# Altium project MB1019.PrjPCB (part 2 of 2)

## Sheet ST_LINK.SCHDOC
size A4; Revision: C.1
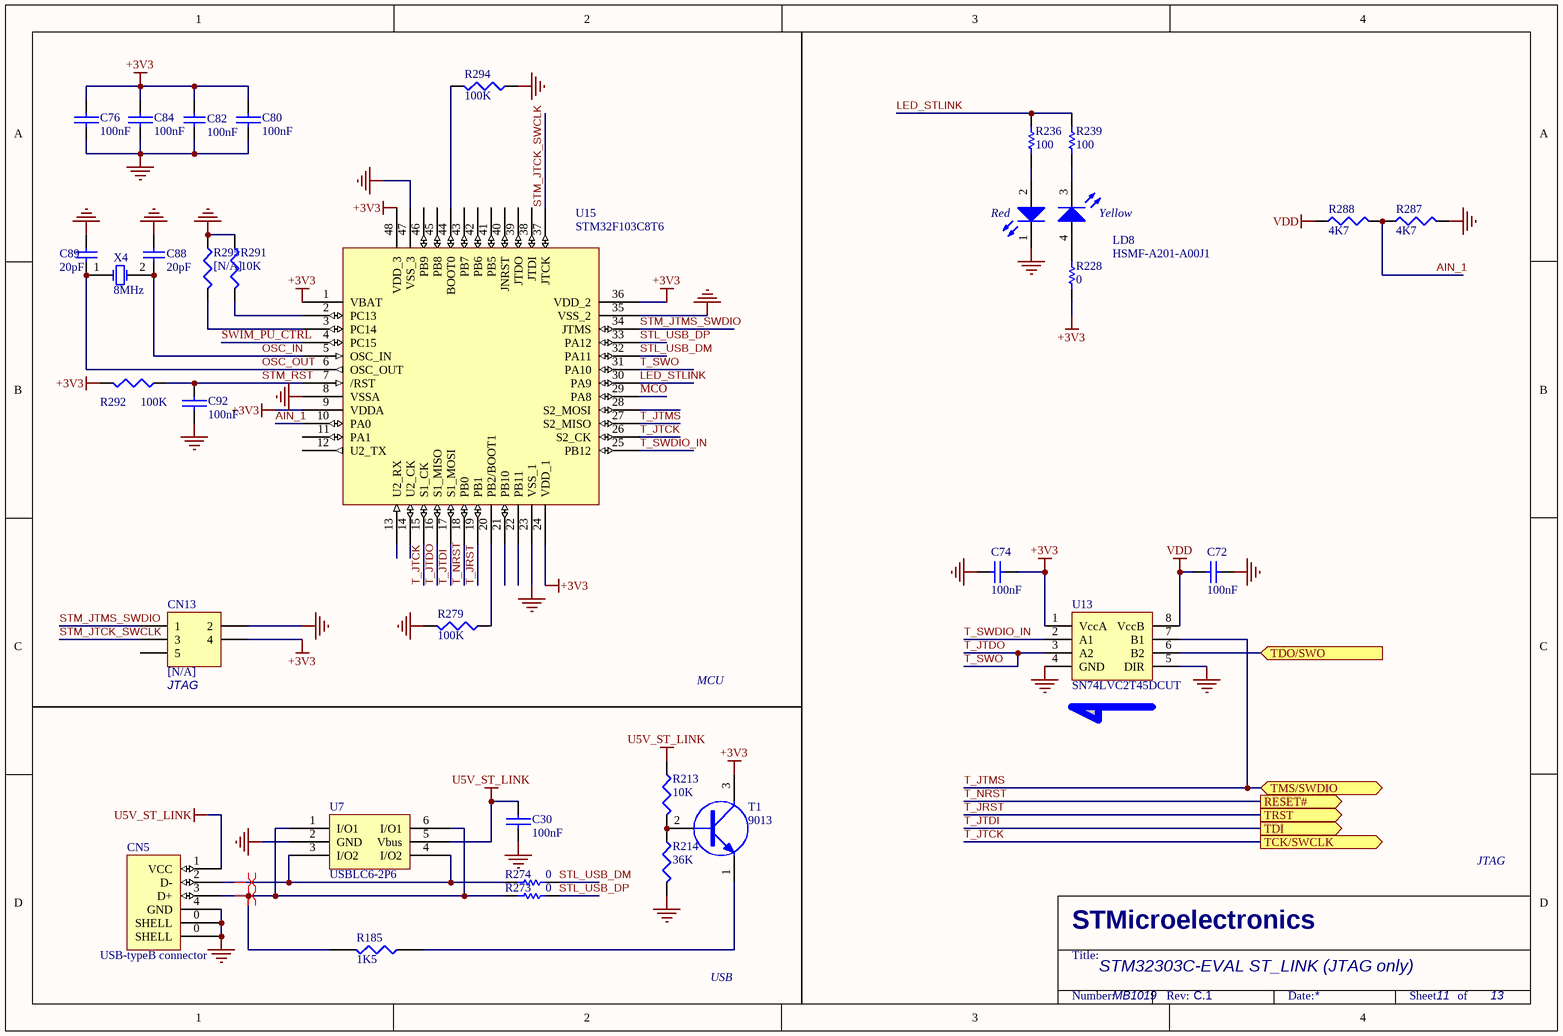
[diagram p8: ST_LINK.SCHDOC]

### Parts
C30  100nF  [0603C]
C72  100nF  [0603C]
C74  100nF  [0603C]
C76  100nF  [0603C]
C80  100nF  [0603C]
C82  100nF  [0603C]
C84  100nF  [0603C]
C88  20pF  [0603C]
C89  20pF  [0603C]
C92  100nF  [0603C]
CN5  USB-typeB connector  [USB-B]
CN13  [N/A]  [2*3P]
LD8  HSMF-A201-A00J1  [LED2-28*32]
R185  1K5  [0603R]
R213  10K  [0603R]
R214  36K  [0603R]
R228  0  [0603R]
R236  100  [0603R]
R239  100  [0603R]
R273  0  [0603R]
R274  0  [0603R]
R279  100K  [0603R]
R287  4K7  [0603R]
R288  4K7  [0603R]
R291  10K  [0603R]
R292  100K  [0603R]
R294  100K  [0603R]
R295  [N/A]  [0603R]
T1  9013  [SOT-23]
U7  USBLC6-2P6  [SOT-666]
U13  SN74LVC2T45DCUT  [VSSOP8]
U15  STM32F103C8T6  [LQFP48]
X4  8MHz  [SMT_XTAL]

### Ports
RESET# (out), TCK/SWCLK (out), TDI (out), TDO/SWO (in), TMS/SWDIO (bidir), TRST (out)

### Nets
+3V3: C74.2 C76.2 C80.2 C82.1 C84.2 CN13.4 R228.2 R292.2 T1.3(C) U13.1(VccA) U15.1(VBAT) U15.9(VDDA) U15.24(VDD_1) U15.36(VDD_2) U15.48(VDD_3)
GND: C30.2 C72.2 C74.1 C76.1 C80.1 C82.2 C84.1 C88.1 C89.1 C92.1 CN5.0(SHELL) CN5.4(GND) CN13.2 LD8.1(RED_cathode) R214.2 R279.2 R287.2 R291.1 R294.1 R295.1 U7.2(GND) U13.4(GND) U13.5(DIR) U15.8(VSSA) U15.23(VSS_1) U15.35(VSS_2) U15.47(VSS_3)
U5V_ST_LINK: C30.1 CN5.1(VCC) R213.1 U7.5(Vbus)
VDD: C72.1 R288.1 U13.8(VccB)
AIN_1: R287.1 R288.2 U15.10(PA0)
LED_STLINK: R236.1 R239.1 U15.30(PA9)
MCO: U15.29(PA8)
OSC_IN: C88.2 U15.5(OSC_IN) X4.2(OSC2)
OSC_OUT: C89.2 U15.6(OSC_OUT) X4.1(OSC1)
PB3: U13.6(B2) ; port TDO/SWO
STL_USB_DM: R274.1 U15.32(PA11)
STL_USB_DP: R273.1 U15.33(PA12)
STM_JTCK_SWCLK: CN13.3 U15.37(JTCK)
STM_JTMS_SWDIO: CN13.1 U15.34(JTMS)
STM_RST: C92.2 R292.1 U15.7(/RST)
SWIM_PU_CTRL: U15.4(PC15)
T_JRST: U15.19(PB1) ; port TRST  [project net PB4]
T_JTCK: U15.15(S1_CK) U15.26(S2_CK) ; port TCK/SWCLK  [project net PA14]
T_JTDI: U15.17(S1_MOSI) ; port TDI  [project net PA15]
T_JTDO: U13.3(A2) U15.16(S1_MISO) U15.31(PA10)  [also labelled T_SWO]
T_JTMS: U13.7(B1) U15.27(S2_MISO) ; port TMS/SWDIO  [project net PA13]
T_NRST: U15.18(PB0) ; port RESET#  [project net RESET#]
T_SWDIO_IN: U13.2(A1) U15.25(PB12)
NetCN5_2: CN5.2(D-) R274.2 U7.3(I/O2) U7.4(I/O2)
NetCN5_3: CN5.3(D+) R185.2 R273.2 U7.1(I/O1) U7.6(I/O1)
NetLD8_2: LD8.2(Red_anode) R236.2
NetLD8_3: LD8.3(YellowGreen_cathode) R239.2
NetLD8_4: LD8.4(YellowGreen_anode) R228.1
NetR185_1: R185.1 T1.1(E)
NetR213_2: R213.2 R214.1 T1.2(B)
NetR279_1: R279.1 U15.20(PB2/BOOT1)
NetR291_2: R291.2 U15.2(PC13)
NetR294_2: R294.2 U15.44(BOOT0)
NetR295_2: R295.2 U15.3(PC14)

Not connected (* = marked no-connect by the designer): CN13 5; U15 11(PA1) 12(U2_TX) 13(U2_RX) 14(U2_CK) 21(PB10) 22(PB11) 28(S2_MOSI) 38(JTDI) 39(JTDO) 40(JNRST) 41(PB5) 42(PB6) 43(PB7) 45(PB8) 46(PB9)

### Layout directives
differential pair: NetCN5_2, NetCN5_3

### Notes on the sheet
- (near CN13) JTAG
- MCU
- JTAG
- USB
- STM32303C-EVAL ST_LINK (JTAG only)
- MB1019
- 11
- 13

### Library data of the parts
C30 = CAP: Capacitor
C72 C74 = CAP: Capacitor; Value: 100pF
C76 C80 C84 C92 = CAP
C82 = Cap: Capacitor; Value: 10nF
C88 C89 = Cap: Capacitor
CN13 = Header 3X2: Header, 3-Pin, Dual row
R185 R279 R287 R288 R292 R294 = RES1
R213 R214 R291 R295 = R: Right: 20; Bottom: 30
R228 R236 R239 R273 R274 = Res1: Resistor; Value: 1K
T1 = NPN
U7 = USBLC6-2
U15 = STM32F10x(48pin)
X4 = XTAL: Crystal Oscillator

## Sheet Power.SchDoc
size A4; Revision: C.1
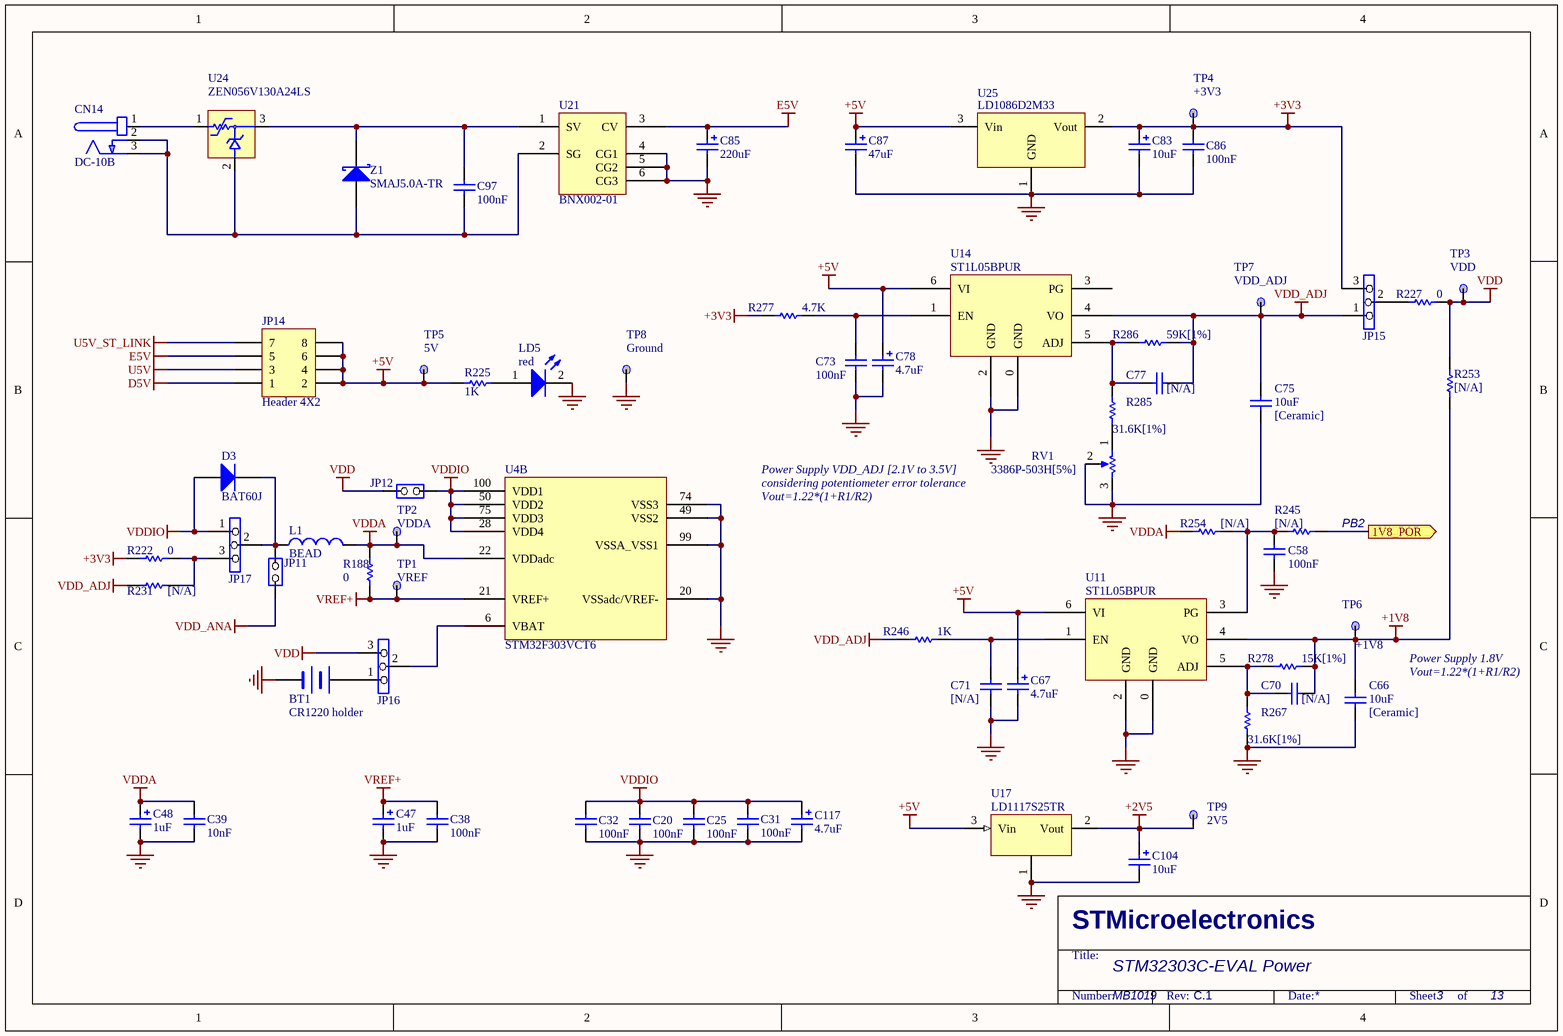
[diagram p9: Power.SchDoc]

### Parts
BT1  CR1220 holder  [LI1220_1]
C20  100nF  [0603C]
C25  100nF  [0603C]
C31  100nF  [0603C]
C32  100nF  [0603C]
C38  100nF  [0603C]
C39  10nF  [0603C]
C47  1uF  [TAN-A]
C48  1uF  [TAN-A]
C58  100nF  [0603C]
C66  10uF  [0805C]
C67  4.7uF  [TAN-A]
C70  [N/A]  [0603C]
C71  [N/A]  [0603C]
C73  100nF  [0603C]
C75  10uF  [0805C]
C77  [N/A]  [0603C]
C78  4.7uF  [TAN-A]
C83  10uF  [TAN-A]
C85  220uF  [C310M]
C86  100nF  [0603C]
C87  47uF  [C200M]
C97  100nF  [0603C]
C104  10uF  [TAN-A]
C117  4.7uF  [TAN-A]
CN14  DC-10B  [DC10B]
D3  BAT60J  [SOD-323]
JP11  (no value)  [SIP2]
JP12  (no value)  [SIP2]
JP14  Header 4X2  [2*4P]
JP15  (no value)  [SIP3]
JP16  (no value)  [SIP3]
JP17  (no value)  [SIP3]
L1  BEAD  [0603L]
LD5  red  [0603D]
R188  0  [0603R]
R222  0  [0603R]
R225  1K  [0603R]
R227  0  [0603R]
R231  [N/A]  [0603R]
R245  [N/A]  [0603R]
R246  1K  [0603R]
R253  [N/A]  [0603R]
R254  [N/A]  [0603R]
R267  31.6K[1%]  [0603R]
R277  4.7K  [0603R]
R278  15K[1%]  [0603R]
R285  31.6K[1%]  [0603R]
R286  59K[1%]  [0603R]
RV1  3386P-503H[5%]  [3296W]
TP1  VREF  [TP]
TP2  VDDA  [TP]
TP3  VDD  [TP]
TP4  +3V3  [TP]
TP5  5V  [TP]
TP6  +1V8  [TP]
TP7  VDD_ADJ  [TP]
TP8  Ground  [TP]
TP9  2V5  [TP]
U4  STM32F303VCT6  [IC149-100-025-B5]  (part B of 2)
U11  ST1L05BPUR  [DFN6(3X3)]
U14  ST1L05BPUR  [DFN6(3X3)]
U17  LD1117S25TR  [SOT-223]
U21  BNX002-01  [BNX001]
U24  ZEN056V130A24LS  [polyzen]
U25  LD1086D2M33  [D2PAK/A]
Z1  SMAJ5.0A-TR  [1R1C]

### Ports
1V8_POR (out)

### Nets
+1V8: C66.1 C70.2 R253.2 R278.1 TP6.1 U11.4(VO)
+2V5: C104.1 TP9.1 U17.2(Vout)
+3V3: C83.1 C86.1 JP15.3 R222.2 R277.2 TP4.1 U25.2(Vout)
+5V: C67.1 C78.1 C87.1 JP14.2 JP14.4 JP14.6 JP14.8 R225.2 TP5.1 U11.6(VI) U14.6(VI) U17.3(Vin) U25.3(Vin)
D5V: JP14.1
E5V: C85.1 JP14.5 U21.3(CV)
GND: BT1.2(-) C20.2 C25.2 C31.1 C32.2 C38.1 C39.1 C47.2 C48.2 C58.2 C66.2 C67.2 C71.2 C73.2 C75.2 C78.2 C83.2 C85.2 C86.2 C87.2 C104.2 C117.2 LD5.2(K) R267.2 RV1.2(TAP) RV1.3(TOP) TP8.1 U4.20(VSSadc/VREF-) U4.49(VSS2) U4.74(VSS3) U4.99(VSSA_VSS1) U11.0(GND) U11.2(GND) U14.0(GND) U14.2(GND) U17.1 U21.4(CG1) U21.5(CG2) U21.6(CG3) U25.1(GND)
U5V: JP14.3
U5V_ST_LINK: JP14.7
VDD: JP12.2(NO) JP16.3 R227.1 R253.1 TP3.1
VDD_ADJ: C75.1 C77.2 JP15.1 R231.2 R246.2 R286.1 TP7.1 U14.4(VO)
VDD_ANA: JP11.1(COMMON)
VDDA: C39.2 C48.1 L1.2 R188.1 R254.1 TP2.1 U4.22(VDDadc)
VDDIO: C20.1 C25.1 C31.2 C32.1 C117.1 D3.1(A) JP12.1(COMMON) JP17.1 U4.28(VDD4) U4.50(VDD2) U4.75(VDD3) U4.100(VDD1)
VREF+: C38.2 C47.1 R188.2 TP1.1 U4.21(VREF+)
PB2: R245.1 ; port 1V8_POR
NetBT1_1: BT1.1(+) JP16.1
NetC58_1: C58.1 R245.2 R254.2 U11.3(PG)
NetC70_1: C70.1 R267.1 R278.2 U11.5(ADJ)
NetC71_1: C71.1 R246.1 U11.1(EN)
NetC73_1: C73.1 R277.1 U14.1(EN)
NetC77_1: C77.1 R285.1 R286.2 U14.5(ADJ)
NetC97_1: C97.1 U21.1(SV) U24.3 Z1.2(K)
NetC97_2: C97.2 CN14.2(GND) CN14.3(GND) U21.2(SG) U24.2 Z1.1(A)
NetCN14_1: CN14.1(+) U24.1
NetD3_2: D3.2(K) JP11.2(NO) JP17.2 L1.1
NetJP15_2: JP15.2 R227.2
NetJP16_2: JP16.2 U4.6(VBAT)
NetJP17_3: JP17.3 R222.1 R231.1
NetLD5_1: LD5.1(A) R225.1
NetR285_2: R285.2 RV1.1(BOT)

Not connected (* = marked no-connect by the designer): U14 3(PG)

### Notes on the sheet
- (near C75) [Ceramic]
- Power Supply VDD_ADJ [2.1V to 3.5V]
- Vout=1.22*(1+R1/R2)
- considering potentiometer error tolerance
- (near R245) PB2
- (near C66) [Ceramic]
- Power Supply 1.8V
- STM32303C-EVAL Power
- MB1019
- 3
- 13

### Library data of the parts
BT1 = BATTERY
C20 C25 C32 = CAP: Capacitor
C31 C38 C58 C66 C70 C71 C73 C75 C77 C86 = Cap: Capacitor; Value: 10nF
C39 = Cap: Capacitor
C47 C48 C87 = Cap Pol1: Polarized Capacitor (Radial); Value: 10uF
C67 C78 C117 = Cap Pol1: Polarized Capacitor (Radial); Value: 100pF
C83 C104 = Cap Pol1: Polarized Capacitor (Radial)
C85 = Cap Pol1: Polarized Capacitor (Radial); Value: 47uF
C97 = CAP: Capacitor; Value: 100pF
CN14 = PJ202A
D3 = Diode: Default Diode; Code - JEDEC: DO-214-AB
JP11 JP12 = JP2
JP14 = Header 4X2: Header, 4-Pin, Dual row
JP15-JP17 = Jumper3
L1 = Inductor: Value: 100uH
LD5 = LED2: Typical RED, GREEN, YELLOW, AMBER GaAs LED
R188 R222 R227 R231 R245 R253 R267 R278 R285 R286 = Res1: Resistor; Value: 1K
R225 R246 = res1: Resistor
R254 R277 = res1: Resistor; Value: 1K
RV1 = RV
TP1-TP9 = TP
U11 U14 = ST1L05
U17 = LD1117
U21 = BNX002
U25 = VOLTREG1
Z1 = D Schottky: Schottky Diode; Code - JEDEC: DO-214-AA

## Sheet Audio.SchDoc
size A4; Revision: C.1
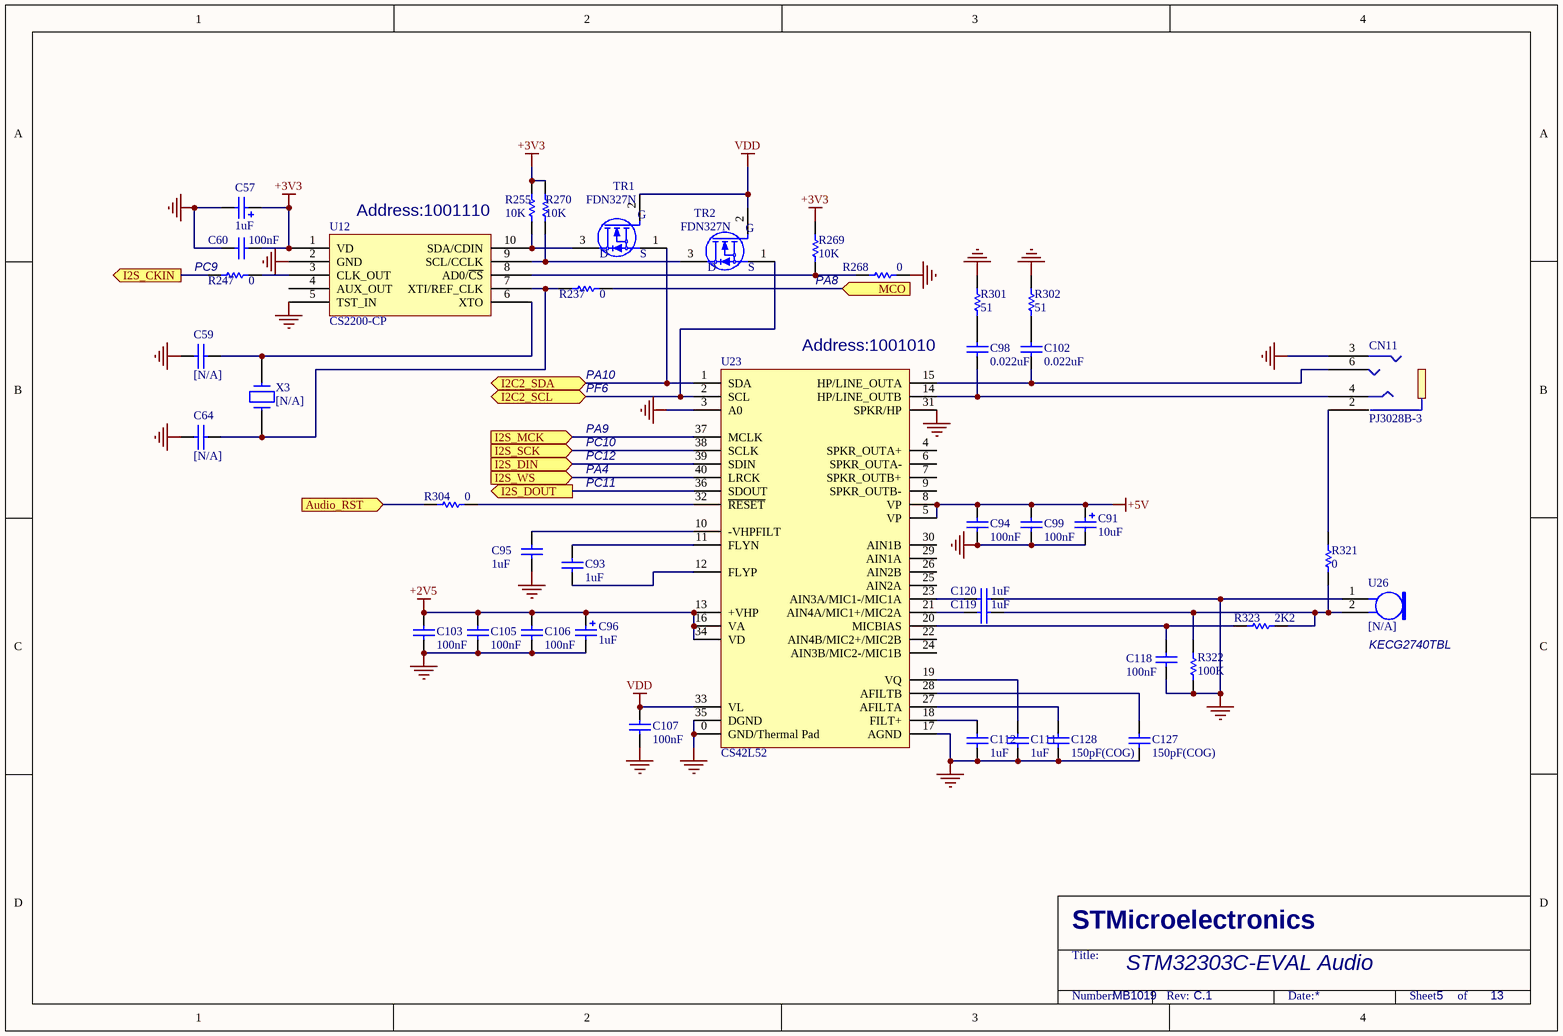
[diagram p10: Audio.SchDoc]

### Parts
C57  1uF  [TAN-A]
C59  [N/A]  [0603C]
C60  100nF  [0603C]
C64  [N/A]  [0603C]
C91  10uF  [TAN-A]
C93  1uF  [0603C]
C94  100nF  [0603C]
C95  1uF  [0603C]
C96  1uF  [TAN-A]
C98  0.022uF  [0603C]
C99  100nF  [0603C]
C102  0.022uF  [0603C]
C103  100nF  [0603C]
C105  100nF  [0603C]
C106  100nF  [0603C]
C107  100nF  [0603C]
C111  1uF  [0603C]
C112  1uF  [0603C]
C118  100nF  [0603C]
C119  1uF  [0603C]
C120  1uF  [0603C]
C127  150pF(COG)  [0603C]
C128  150pF(COG)  [0603C]
CN11  PJ3028B-3  [PJ3028B]
R237  0  [0603R]
R247  0  [0603R]
R255  10K  [0603R]
R268  0  [0603R]
R269  10K  [0603R]
R270  10K  [0603R]
R301  51  [0603R]
R302  51  [0603R]
R304  0  [0603R]
R321  0  [0603R]
R322  100K  [0603R]
R323  2K2  [0603R]
TR1  FDN327N  [SOT-23]
TR2  FDN327N  [SOT-23]
U12  CS2200-CP  [MSOP10(0.5)]
U23  CS42L52  [QFN40(6*6)]
U26  [N/A]  [KEC2740]
X3  [N/A]  [XTAL_socket]

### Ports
Audio_RST (in), I2C2_SCL (bidir), I2C2_SDA (bidir), I2S_CKIN (out), I2S_DIN (in), I2S_DOUT (out), I2S_MCK (in), I2S_SCK (in), I2S_WS (in), MCO (in)

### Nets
+2V5: C96.1 C103.1 C105.1 C106.1 U23.13(+VHP) U23.16(VA) U23.34(VD)
+3V3: C57.1 C60.1 R255.1 R269.1 R270.1 U12.1(VD)
+5V: C91.1 C94.1 C99.1 U23.5(VP) U23.8(VP)
GND: C57.2 C59.2 C60.2 C64.2 C91.2 C94.2 C95.2 C96.2 C99.2 C103.2 C105.2 C106.2 C107.2 C111.1 C112.1 C118.2 C120.2 C127.1 C128.1 CN11.3 R268.1 R301.1 R302.1 R322.2 U12.2(GND) U12.5(TST_IN) U23.0(GND/Thermal_Pad) U23.3(A0) U23.17(AGND) U23.31(SPKR/HP) U23.35(DGND) U26.1
VDD: C107.1 TR1.2(G) TR2.2(G) U23.33(VL)
PA8: R237.1 ; port MCO
PC9: R247.2 ; port I2S_CKIN
RESET#: R304.2 ; port Audio_RST
NetC59_1: C59.1 U12.6(XTO) X3.2
NetC64_1: C64.1 R237.2 U12.7(XTI/REF_CLK) X3.1
NetC93_1: C93.1 U23.12(FLYP)
NetC93_2: C93.2 U23.11(FLYN)
NetC95_1: C95.1 U23.10(-VHPFILT)
NetC98_1: C98.1 R301.2
NetC98_2: C98.2 CN11.4 U23.14(HP/LINE_OUTB)
NetC102_1: C102.1 R302.2
NetC102_2: C102.2 CN11.6 U23.15(HP/LINE_OUTA)
NetC111_2: C111.2 U23.19(VQ)
NetC112_2: C112.2 U23.18(FILT+)
NetC118_1: C118.1 R323.2 U23.20(MICBIAS)
NetC119_1: C119.1 U23.21(AIN4A/MIC1+/MIC2A)
NetC119_2: C119.2 R321.1 R322.1 R323.1 U26.2
NetC120_1: C120.1 U23.23(AIN3A/MIC1-/MIC1A)
NetC127_2: C127.2 U23.28(AFILTB)
NetC128_2: C128.2 U23.27(AFILTA)
NetCN11_2: CN11.2 R321.2
NetJP5_1: TR1.1(S) U23.1(SDA) ; port I2C2_SDA
NetJP6_1: TR2.1(S) U23.2(SCL) ; port I2C2_SCL
NetJP18_1: U23.37(MCLK) ; port I2S_MCK
NetR16_2: U23.40(LRCK) ; port I2S_WS
NetR52_1: U23.38(SCLK) ; port I2S_SCK
NetR54_1: U23.36(SDOUT) ; port I2S_DOUT
NetR56_1: U23.39(SDIN) ; port I2S_DIN
NetR247_1: R247.1 U12.3(CLK_OUT)
NetR255_2: R255.2 TR1.3(D) U12.10(SDA/CDIN)
NetR268_2: R268.2 R269.2 U12.8(AD0/~{CS})
NetR270_2: R270.2 TR2.3(D) U12.9(SCL/CCLK)
NetR304_1: R304.1 U23.32(~{RESET})

Not connected (* = marked no-connect by the designer): U12 4(AUX_OUT); U23 4(SPKR_OUTA+) 6(SPKR_OUTA-) 7(SPKR_OUTB+) 9(SPKR_OUTB-) 22(AIN4B/MIC2+/MIC2B) 24(AIN3B/MIC2-/MIC1B) 25(AIN2A) 26(AIN2B) 29(AIN1A) 30(AIN1B)

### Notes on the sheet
- (near U12) Address:1001110
- (near R247) PC9
- (near R269) PA8
- PA10
- (near U23) Address:1001010
- PA9
- PC10
- PF6
- PA4
- PC12
- PC11
- (near U26) KECG2740TBL
- STM32303C-EVAL Audio
- MB1019
- 5
- 13

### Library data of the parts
C57 C96 = Cap Pol1: as C85 on sheet Power
C59 C60 C64 = CAP: Capacitor
C91 = Cap Pol1: Polarized Capacitor (Radial)
C93 C95 C98 C102 C111 C112 C119 C120 C127 C128 = CAP: Capacitor; Value: 100nF
C94 C99 C103 C105-C107 C118 = Cap: Capacitor; Value: 10nF
R237 R268 R301 R302 R321 R322 = res1: Resistor; Value: 1K
R247 R255 R269 R270 R304 R323 = Res1: Resistor; Value: 1K
TR1 TR2 = 2N7000
U26 = Mic2: Microphone
X3 = CRYSTAL

## Sheet I2C Peripherals.SCHDOC
size A4; Revision: C.1
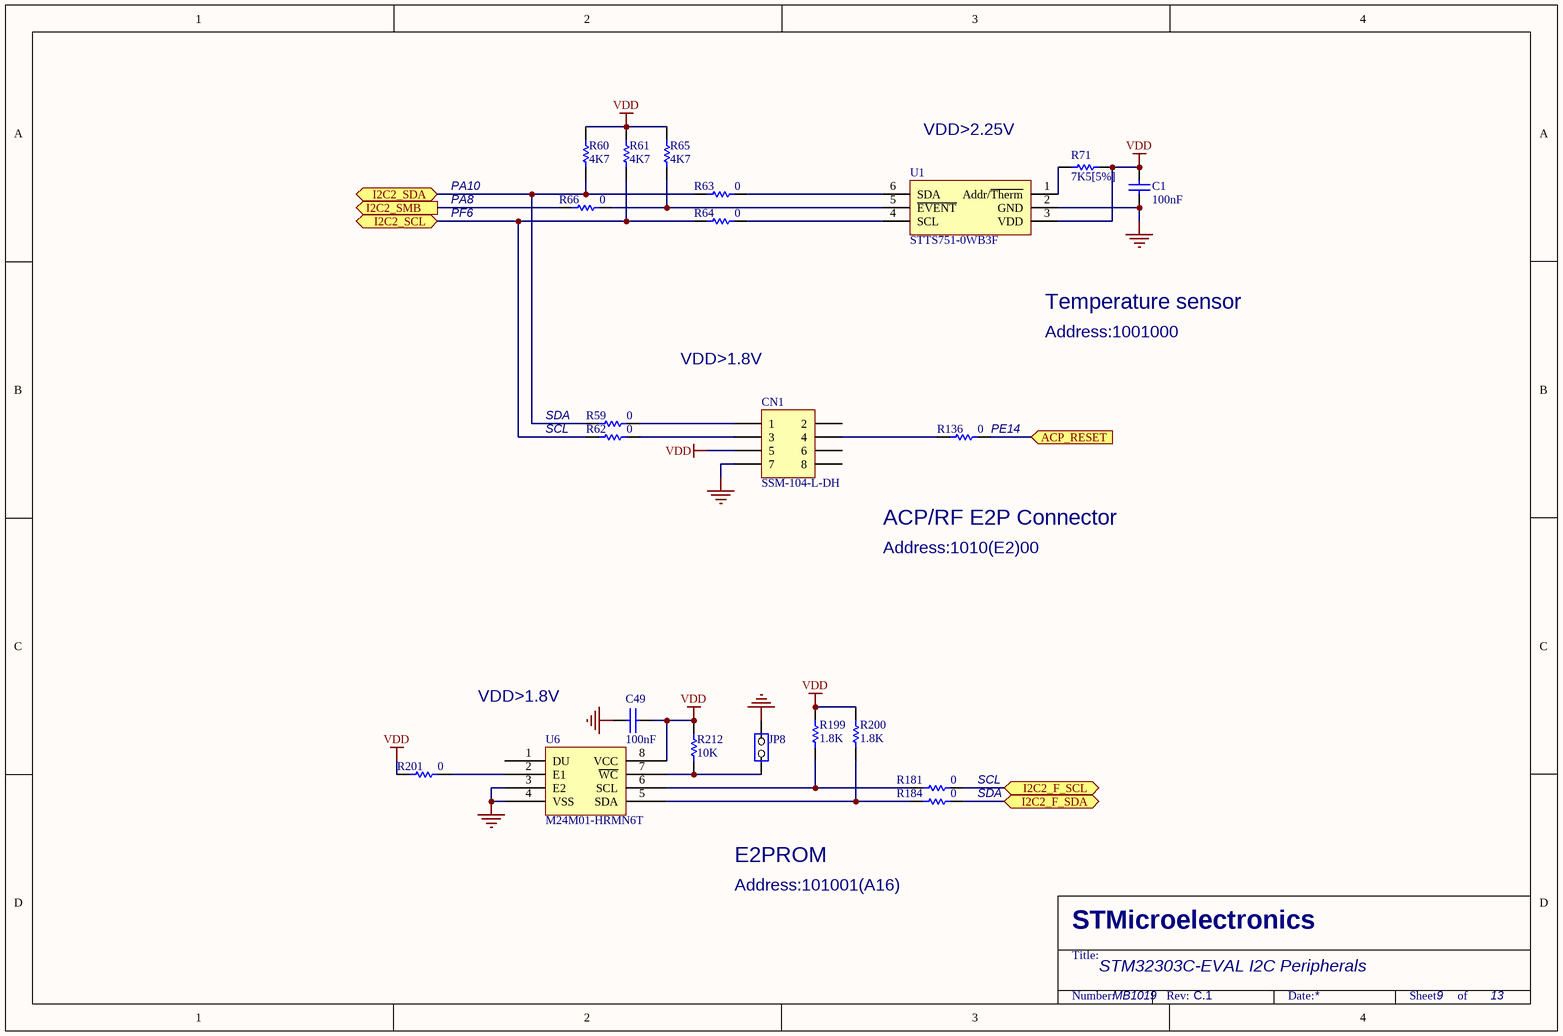
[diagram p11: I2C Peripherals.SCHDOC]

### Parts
C1  100nF  [0603C]
C49  100nF  [0603C]
CN1  SSM-104-L-DH  [SSM-104-L-DH]
JP8  (no value)  [SIP2]
R59  0  [0603R]
R60  4K7  [0603R]
R61  4K7  [0603R]
R62  0  [0603R]
R63  0  [0603R]
R64  0  [0603R]
R65  4K7  [0603R]
R66  0  [0603R]
R71  7K5[5%]  [0603R]
R136  0  [0603R]
R181  0  [0603R]
R184  0  [0603R]
R199  1.8K  [0603R]
R200  1.8K  [0603R]
R201  0  [0603R]
R212  10K  [0603R]
U1  STTS751-0WB3F  [SOT23-6L]
U6  M24M01-HRMN6T  [SO8]

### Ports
ACP_RESET (in), I2C2_F_SCL (bidir), I2C2_F_SDA (bidir), I2C2_SCL (bidir), I2C2_SDA (bidir), I2C2_SMB (out)

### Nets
GND: C1.1 C49.1 CN1.7 JP8.2(NO) U1.2(GND) U6.3(E2) U6.4(VSS)
VDD: C1.2 C49.2 CN1.5 R60.2 R61.2 R65.2 R71.1 R199.2 R200.2 R201.1 R212.1 U1.3(VDD) U6.8(VCC)
PE14: R136.1 ; port ACP_RESET
NetCN1_1: CN1.1 R59.2
NetCN1_3: CN1.3 R62.2
NetCN1_4: CN1.4 R136.2
NetJP1_2: R66.2 ; port I2C2_SMB
NetJP5_1: R59.1 R60.1 R63.1 ; port I2C2_SDA
NetJP5_3: R184.2 ; port I2C2_F_SDA
NetJP6_1: R61.1 R62.1 R64.1 ; port I2C2_SCL
NetJP6_3: R181.2 ; port I2C2_F_SCL
NetJP8_1: JP8.1(COMMON) R212.2 U6.7(~{WC})
NetR63_2: R63.2 U1.6(SDA)
NetR64_2: R64.2 U1.4(SCL)
NetR65_1: R65.1 R66.1 U1.5(~{EVENT})
NetR71_2: R71.2 U1.1(Addr/~{Therm})
NetR181_1: R181.1 R199.1 U6.6(SCL)
NetR184_1: R184.1 R200.1 U6.5(SDA)
NetR201_2: R201.2 U6.2(E1)

Not connected (* = marked no-connect by the designer): CN1 2 6 8; U6 1(DU)

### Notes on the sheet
- VDD>2.25V
- PA10
- PA8
- PF6
- Temperature sensor
- VDD>1.8V
- Address:1001000
- SDA
- SCL
- (near R136) PE14
- Address:1010(E2)00
- ACP/RF E2P Connector
- Address:101001(A16)
- E2PROM
- STM32303C-EVAL I2C Peripherals
- MB1019
- 9
- 13

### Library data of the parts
C1 = cap: Capacitor; Value: 100pF
C49 = CAP: Capacitor
CN1 = SSM-104-L-DH: Header, 5-Pin, Dual row
JP8 = JP2
R59-R66 R71 R136 R181 R184 R199-R201 = Res1: Resistor; Value: 1K
R212 = res1: Resistor; Value: 1K
U6 = M24M01

## Sheet LCD_MicroSD_Flash.SchDoc
size A4; Revision: C.1
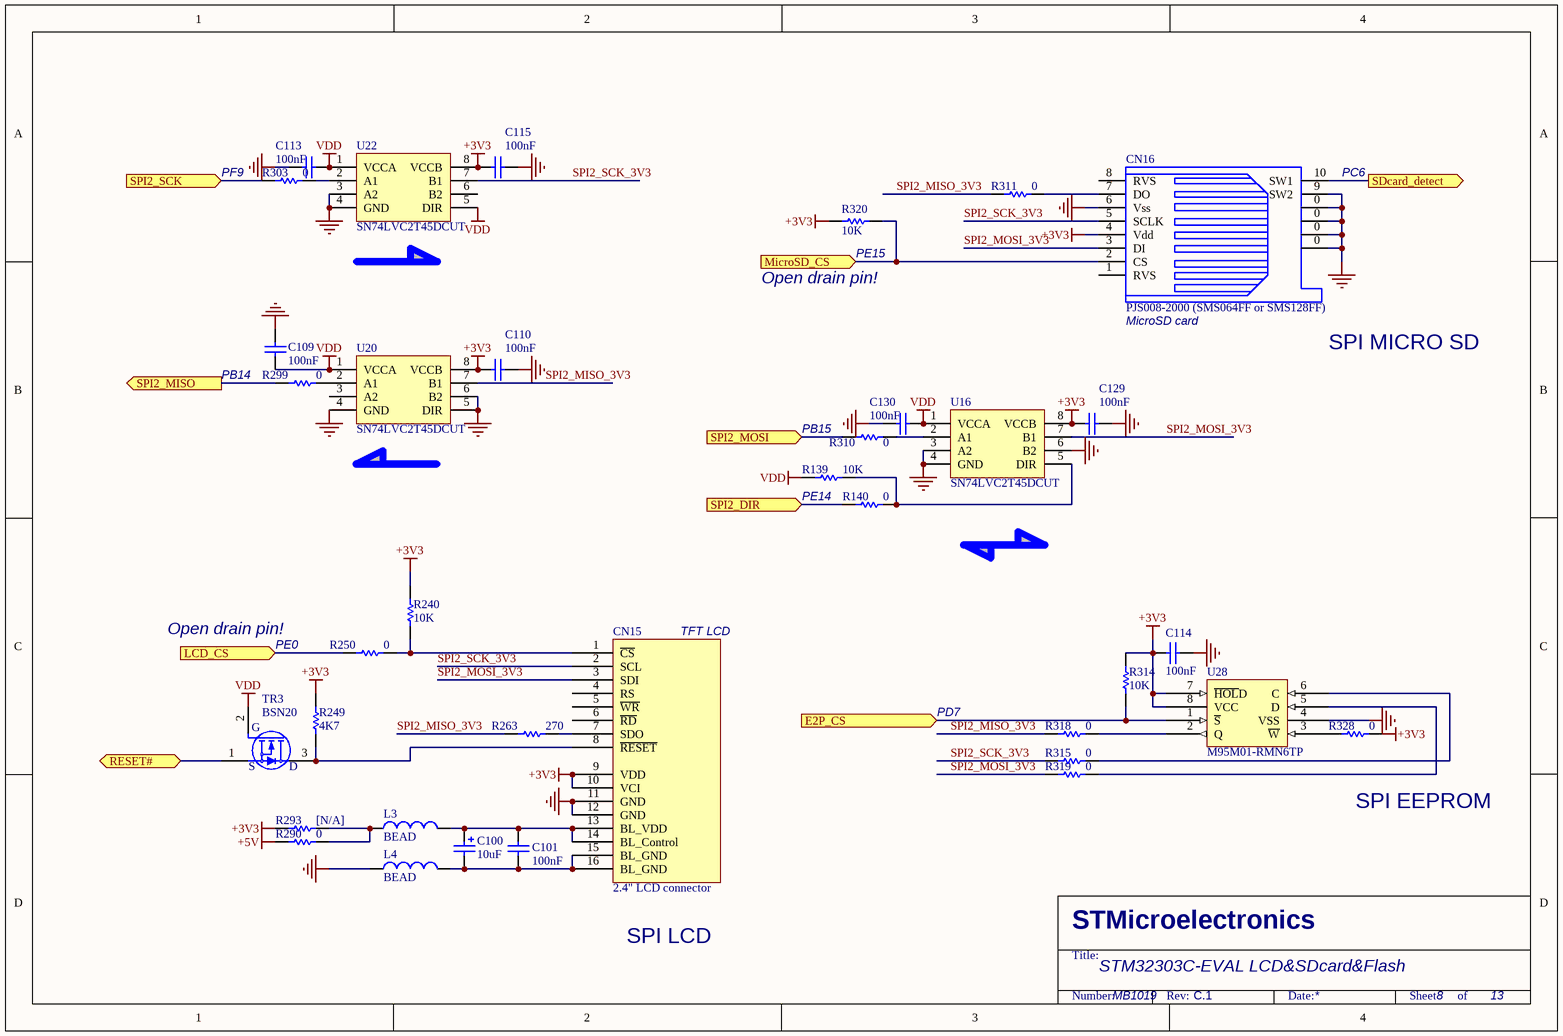
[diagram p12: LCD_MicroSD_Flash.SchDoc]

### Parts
C100  10uF  [TAN-A]
C101  100nF  [0603C]
C109  100nF  [0603C]
C110  100nF  [0603C]
C113  100nF  [0603C]
C114  100nF  [0603C]
C115  100nF  [0603C]
C129  100nF  [0603C]
C130  100nF  [0603C]
CN15  2.4" LCD connector  [MB895CS]
CN16  PJS008-2000 (SMS064FF or SMS128FF)  [MSD(PJS008)]
L3  BEAD  [0603L]
L4  BEAD  [0603L]
R139  10K  [0603R]
R140  0  [0603R]
R240  10K  [0603R]
R249  4K7  [0603R]
R250  0  [0603R]
R263  270  [0603R]
R290  0  [0603R]
R293  [N/A]  [0603R]
R299  0  [0603R]
R303  0  [0603R]
R310  0  [0603R]
R311  0  [0603R]
R314  10K  [0603R]
R315  0  [0603R]
R318  0  [0603R]
R319  0  [0603R]
R320  10K  [0603R]
R328  0  [0603R]
TR3  BSN20  [SOT-23]
U16  SN74LVC2T45DCUT  [VSSOP8]
U20  SN74LVC2T45DCUT  [VSSOP8]
U22  SN74LVC2T45DCUT  [VSSOP8]
U28  M95M01-RMN6TP  [SO8]

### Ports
E2P_CS (in), LCD_CS (in), MicroSD_CS (in), RESET# (bidir), SDcard_detect (out), SPI2_DIR (in), SPI2_MISO (out), SPI2_MOSI (in), SPI2_SCK (in)

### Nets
+3V3: C110.2 C114.1 C115.2 C129.2 CN15.9(VDD) CN15.10(VCI) CN16.4(Vdd) R240.2 R249.2 R293.1 R314.1 R320.2 R328.1 U16.8(VCCB) U20.8(VCCB) U22.8(VCCB) U28.7(~{HOL}D) U28.8(VCC)
+5V: R290.1
GND: C109.1 C110.1 C113.1 C114.2 C115.1 C129.1 C130.1 CN15.11(GND) CN15.12(GND) CN16.0 CN16.6(Vss) CN16.9(SW2) L4.1 U16.3(A2) U16.4(GND) U16.6(B2) U20.4(GND) U20.5(DIR) U20.6(B2) U22.3(A2) U22.4(GND) U28.4(VSS)
VDD: C109.2 C113.2 C130.2 R139.2 TR3.2(G) U16.1(VCCA) U20.1(VCCA) U22.1(VCCA) U22.5(DIR)
PB14: R299.1 ; port SPI2_MISO
PB15: R310.2 ; port SPI2_MOSI
PE0: R250.1 ; port LCD_CS
PE14: R140.2 ; port SPI2_DIR
PF9: R303.2 ; port SPI2_SCK
RESET#: TR3.1(S) ; port RESET#
SPI2_MISO_3V3: R263.1 R311.1 R318.2 U20.7(B1)
SPI2_MOSI_3V3: CN15.3(SDI) CN16.3(DI) R319.2 U16.7(B1)
SPI2_SCK_3V3: CN15.2(SCL) CN16.5(SCLK) R315.2 U22.7(B1)
NetC100_1: C100.1 C101.1 CN15.13(BL_VDD) CN15.14(BL_Control) L3.2
NetC100_2: C100.2 C101.2 CN15.15(BL_GND) CN15.16(BL_GND) L4.2
NetCN15_1: CN15.1(~{CS}) R240.1 R250.2
NetCN15_7: CN15.7(SDO) R263.2
NetCN15_8: CN15.8(~{RESET}) R249.1 TR3.3(D)
NetCN16_2: CN16.2(CS) R320.1 ; port MicroSD_CS
NetCN16_7: CN16.7(DO) R311.2
NetCN16_10: CN16.10(SW1) ; port SDcard_detect
NetL3_1: L3.1 R290.2 R293.2
NetR58_1: R314.2 U28.1(~{S}) ; port E2P_CS
NetR139_1: R139.1 R140.1 U16.5(DIR)
NetR299_2: R299.2 U20.2(A1)
NetR303_1: R303.1 U22.2(A1)
NetR310_1: R310.1 U16.2(A1)
NetR315_1: R315.1 U28.6(C)
NetR318_1: R318.1 U28.2(Q)
NetR319_1: R319.1 U28.5(D)
NetR328_2: R328.2 U28.3(~{W})

Not connected (* = marked no-connect by the designer): CN15 4(RS) 5(~{WR}) 6(~{RD}); CN16 1(RVS) 8(RVS); U20 3(A2); U22 6(B2)

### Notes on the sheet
- (near R303) PF9
- (near CN16) PC6
- (near R320) Open drain pin!
- (near R320) PE15
- PB14
- (near CN16) MicroSD card
- SPI MICRO SD
- PB15
- (near R139) PE14
- Open drain pin!
- PE0
- TFT LCD
- PD7
- SPI EEPROM
- SPI LCD
- STM32303C-EVAL LCD&SDcard&Flash
- MB1019
- 8
- 13

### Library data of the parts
C100 = Cap Pol1: Polarized Capacitor (Radial)
C101 C114 = Cap: Capacitor; Value: 10nF
C109 C110 C113 C115 C129 C130 = CAP: Capacitor; Value: 100pF
CN15 = ColorLCD_module
CN16 = SMS016AFA5E
L3 L4 = Inductor: Value: 100uH
R139 R140 R240 R249 R250 R263 R290 R293 R299 R311 R315 R318-R320 R328 = Res1: Resistor; Value: 1K
R303 R310 R314 = res1: Resistor; Value: 1K
TR3 = 2N7000
U28 = M95040-R

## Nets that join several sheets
+2V5: Power (C104.1 TP9.1 U17.2), Audio (7 pins)
+3V3: MCU (CN6.48), MotorCtrl (10 pins), RS232_RS485_IrDA (12 pins), Peripherals (LD1.1 LD2.1 LD3.1 LD4.1), CAN&Humidity_Sensor&HB_LED&IR (6 pins), ST_LINK (15 pins), Power (7 pins), Audio (6 pins), LCD_MicroSD_Flash (18 pins)
+5V: MotorCtrl (CN2.25 CN4.25), CAN&Humidity_Sensor&HB_LED&IR (R258.1 T3.1), Power (13 pins), Audio (5 pins), LCD_MicroSD_Flash (R290.1)
D5V: MCU (CN6.49 CN7.19), Power (JP14.1)
GND: MCU (19 pins), MotorCtrl (45 pins), RS232_RS485_IrDA (19 pins), Touch Sensing (C24.1 C52.1), Peripherals (19 pins), CAN&Humidity_Sensor&HB_LED&IR (21 pins), JTAG&Trace (27 pins), ST_LINK (27 pins), Power (40 pins), Audio (32 pins), I2C Peripherals (7 pins), LCD_MicroSD_Flash (22 pins)
U5V: Peripherals (C63.1 CN12.1 R283.1 U19.5), Power (JP14.3)
U5V_ST_LINK: ST_LINK (C30.1 CN5.1 R213.1 U7.5), Power (JP14.7)
VDD: MCU (CN7.24 SW1.1), RS232_RS485_IrDA (5 pins), Peripherals (R276.2 R312.2 R326.1 T6.3), CAN&Humidity_Sensor&HB_LED&IR (R264.1 R271.2), JTAG&Trace (8 pins), ST_LINK (C72.1 R288.1 U13.8), Power (5 pins), Audio (C107.1 TR1.2 TR2.2 U23.33), I2C Peripherals (13 pins), LCD_MicroSD_Flash (9 pins)
VDD_ANA: Peripherals (R158.2 RV2.1), Power (JP11.1)
MC1_MC2_PFC_Ind: MCU (CN7.12 U4.55), MotorCtrl (C22.2 C23.2 R119.1 R123.1)
MC1_MC2_PFC_SD: MCU (CN6.23 U4.83), MotorCtrl (R153.1 R165.1)
MC1_MC2_PFC_Vac: MCU (CN7.7 U4.56), MotorCtrl (C7.2 C26.2 R80.1 R146.1)
MC1_MC2_PFCpwm: MCU (R3.1), MotorCtrl (R145.2 R148.2)
MC1_MC2_PFCsync: MCU (R1.1), MotorCtrl (R81.2 R147.2)
NetC2_2: MCU (R33.1), MotorCtrl (C2.2 CN2.1 R72.1)
NetC3_1: MCU (R9.2), MotorCtrl (C3.1 R67.1)
NetC13_2: MCU (R57.1), MotorCtrl (C13.2 CN2.34)
NetC14_1: MCU (R13.1), MotorCtrl (C14.1 R91.1)
NetC19_2: MCU (R11.2), MotorCtrl (C19.2 CN4.26)
NetC21_1: MCU (R37.2), MotorCtrl (C21.1 R131.1)
NetC27_2: MCU (R41.1), MotorCtrl (C27.2 CN4.33)
NetC28_2: MCU (R17.2), MotorCtrl (C28.2 CN4.34)
NetC29_2: MCU (R21.2), MotorCtrl (C29.2 R133.2 R135.2)
NetC52_2: MCU (R40.1), Touch Sensing (C52.2 SB8.2)
NetC68_1: MCU (R46.1), CAN&Humidity_Sensor&HB_LED&IR (C68.1 D4.2 R248.1)
NetC133_1: MCU (R45.1), MotorCtrl (C133.1 R90.2 R94.1)
NetC134_1: MCU (R35.2), MotorCtrl (C134.1 R128.1 R138.2)
NetC136_1: MCU (R19.2), MotorCtrl (C136.1 R108.2 R120.1)
NetCN2_3: MCU (R25.1), MotorCtrl (CN2.3)
NetCN2_5: MCU (R23.1), MotorCtrl (CN2.5)
NetCN2_7: MCU (R29.1), MotorCtrl (CN2.7)
NetCN2_9: MCU (R27.1), MotorCtrl (CN2.9)
NetCN2_11: MCU (R31.1), MotorCtrl (CN2.11)
NetCN2_21: MCU (R5.1), MotorCtrl (CN2.21)
NetCN2_23: MCU (R7.1), MotorCtrl (CN2.23)
NetCN4_3: MCU (R47.1), MotorCtrl (CN4.3)
NetCN4_5: MCU (R51.1), MotorCtrl (CN4.5)
NetCN4_9: MCU (R53.1), MotorCtrl (CN4.9)
NetCN4_11: MCU (R49.1), MotorCtrl (CN4.11)
NetCN4_13: MCU (R55.1), MotorCtrl (CN4.13)
NetCN4_21: MCU (R43.1), MotorCtrl (CN4.21)
NetCN6_51: MCU (CN6.51), Touch Sensing (SB11.1)
NetCN6_52: MCU (CN6.52), Touch Sensing (SB9.1)
NetCN7_2: MCU (CN7.2), Touch Sensing (SB7.1)
NetCN7_4: MCU (CN7.4), Touch Sensing (SB6.1)
NetCN7_6: MCU (CN7.6), Touch Sensing (SB8.1)
NetCN9_12: MCU (R2.1), JTAG&Trace (CN9.12)
NetCN9_18: MCU (R8.1), JTAG&Trace (CN9.18)
NetCN16_2: MCU (R34.1), LCD_MicroSD_Flash (CN16.2 R320.1)
NetCN16_10: MCU (R48.1), LCD_MicroSD_Flash (CN16.10)
NetD2_1: MCU (D2.1), RS232_RS485_IrDA (R202.1)
NetJP1_2: MCU (JP1.2), I2C Peripherals (R66.2)
NetJP5_1: MB1019 (JP5.1 R183.1), Audio (TR1.1 U23.1), I2C Peripherals (R59.1 R60.1 R63.1)
NetJP5_3: MB1019 (JP5.3 R182.1), I2C Peripherals (R184.2)
NetJP6_1: MB1019 (JP6.1 R180.1), Audio (TR2.1 U23.2), I2C Peripherals (R61.1 R62.1 R64.1)
NetJP6_3: MB1019 (JP6.3 R179.1), I2C Peripherals (R181.2)
NetJP10_2: MCU (JP10.2), RS232_RS485_IrDA (R215.1)
NetJP18_1: MCU (JP18.1), Audio (U23.37)
NetJP18_3: MCU (JP18.3), CAN&Humidity_Sensor&HB_LED&IR (R300.1)
NetJP19_2: MCU (R20.2), CAN&Humidity_Sensor&HB_LED&IR (JP19.2 R159.1)
NetPG3SA_2: MCU (R15.2), MotorCtrl (PG3SA.2 PGM1.3 PGM1.6)
NetR4_1: MCU (R4.1), JTAG&Trace (R242.2)
NetR6_1: MCU (R6.1), JTAG&Trace (R216.2)
NetR10_2: MCU (R10.2), Peripherals (R158.1 R164.2)
NetR14_1: MCU (R14.1), Peripherals (RV2.2)
NetR16_2: MCU (R16.2), Audio (U23.40)
NetR18_2: MCU (R18.2), Peripherals (R265.2 R276.1 T7.2)
NetR24_1: MCU (R24.1), Peripherals (R317.1)
NetR26_1: MCU (R26.1), Peripherals (R306.1)
NetR28_1: MCU (R28.1), Peripherals (R325.1)
NetR30_1: MCU (R30.1), Peripherals (R305.1)
NetR32_1: MCU (R32.1), CAN&Humidity_Sensor&HB_LED&IR (R256.2 R257.1)
NetR36_2: MCU (R36.2), Touch Sensing (R137.1 SB11.2)
NetR38_2: MCU (R38.2), Touch Sensing (R103.1 SB9.2)
NetR39_1: MCU (R39.1), MotorCtrl (R96.1)
NetR42_1: MCU (R42.1), Touch Sensing (R104.1 SB6.2)
NetR44_1: MCU (R44.1), Touch Sensing (R122.2)
NetR50_1: MCU (R50.1), CAN&Humidity_Sensor&HB_LED&IR (R159.2)
NetR52_1: MCU (R52.1), Audio (U23.38)
NetR54_1: MCU (R54.1), Audio (U23.36)
NetR56_1: MCU (R56.1), Audio (U23.39)
NetR58_1: MCU (R58.1), LCD_MicroSD_Flash (R314.2 U28.1)
NetR111_1: MCU (R111.1), Peripherals (R313.2)
NetR129_1: MCU (R129.1), RS232_RS485_IrDA (R186.1 U8.3)
PA1: MCU (CN7.44 U4.24), MotorCtrl (R74.1)
PA2: MCU (CN7.43 U4.25), MotorCtrl (C37.1 R115.1)
PA3: MCU (CN7.42 U4.26), MotorCtrl (C37.2 R114.2 R115.2)
PA5: MCU (CN7.38 U4.30), MotorCtrl (PG3SA.5 PGM2.6 PGM2.9)
PA6: MCU (CN7.37 U4.31), MotorCtrl (C33.1 R118.1)
PA7: MCU (CN7.36 U4.32), MotorCtrl (R75.1)
PA8: MCU (CN6.6 JP1.1 U4.67), Audio (R237.1)
PA10: MB1019 (JP5.2 R182.2 R183.2), MCU (CN6.7 U4.69)
PA11: MCU (CN6.9 U4.70), Peripherals (R266.1)
PA12: MCU (CN6.12 U4.71), Peripherals (R260.1)
PA13: MCU (CN6.13 U4.72), JTAG&Trace (RS1.13), ST_LINK (U13.7 U15.27)
PA14: MCU (CN6.16 U4.76), JTAG&Trace (RS1.11), ST_LINK (U15.15 U15.26)
PA15: MCU (CN6.17 U4.77), JTAG&Trace (RS1.7), ST_LINK (U15.17)
PB1: MCU (CN7.32 U4.36), MotorCtrl (C29.1 R135.1)
PB2: MCU (CN7.31 R21.1 U4.37), Power (R245.1)
PB3: MCU (CN6.32 U4.89), JTAG&Trace (RS1.9), ST_LINK (U13.6)
PB4: MCU (CN6.31 U4.90), JTAG&Trace (RS1.5), ST_LINK (U15.19)
PB5: MCU (CN6.34 U4.91), Peripherals (R307.2)
PB6: MCU (CN6.33 U4.92), MotorCtrl (C35.2 CN4.31 JP7.1)
PB7: MCU (CN6.36 U4.93), MotorCtrl (R79.2)
PB9: MCU (CN6.38 U4.96), CAN&Humidity_Sensor&HB_LED&IR (R262.2)
PB10: MCU (CN7.16 U4.47), MotorCtrl (C21.2 R130.2 R131.2)
PB13: MCU (CN7.15 U4.52), MotorCtrl (R110.1)
PB14: MCU (CN7.14 U4.53), LCD_MicroSD_Flash (R299.1)
PB15: MCU (CN7.13 U4.54), LCD_MicroSD_Flash (R310.2)
PC0: MCU (CN7.51 U4.15), MotorCtrl (R85.2)
PC2: MCU (CN7.48 U4.17), MotorCtrl (R84.1)
PC3: MCU (CN7.47 U4.18), MotorCtrl (R77.1)
PC4: MCU (CN7.35 U4.33), RS232_RS485_IrDA (R177.2)
PC5: MCU (CN7.34 U4.34), MotorCtrl (C33.2 R117.2 R118.2)
PC7: MCU (CN6.3 U4.64), MotorCtrl (CN4.7)
PC9: MCU (CN6.5 U4.66), Audio (R247.2)
PC13: MCU (R187.1 U4.7), Peripherals (R308.2)
PD0: MCU (CN6.21 U4.81), CAN&Humidity_Sensor&HB_LED&IR (R124.1)
PD1: MCU (CN6.24 U4.82), CAN&Humidity_Sensor&HB_LED&IR (R105.2)
PD3: MCU (CN6.26 U4.84), MotorCtrl (C10.2 CN2.31 JP2.1)
PD4: MCU (CN6.25 U4.85), MotorCtrl (C12.2 CN2.33)
PD5: MCU (CN6.28 U4.86), Peripherals (R22.1)
PD6: MCU (CN6.27 U4.87), Peripherals (R12.1)
PD10: MCU (CN7.8 U4.57), MotorCtrl (R100.1)
PD11: MCU (CN7.5 U4.58), MotorCtrl (R92.1)
PE0: MCU (CN6.37 U4.97), LCD_MicroSD_Flash (R250.1)
PE1: MCU (CN6.40 U4.98), RS232_RS485_IrDA (JP13.2 JP13.4 JP13.6)
PE6: MCU (CN6.46 R111.2 U4.5), JTAG&Trace (CN9.20)
PE7: MCU (CN7.29 U4.38), Peripherals (R309.2)
PE12: MCU (CN7.21 U4.43), MotorCtrl (CN2.13)
PE14: MCU (CN7.18 U4.45), I2C Peripherals (R136.1), LCD_MicroSD_Flash (R140.2)
PF4: MCU (CN7.41 U4.27), MotorCtrl (C8.2 R82.2)
PF6: MB1019 (JP6.2 R179.2 R180.2), MCU (CN6.14 U4.73)
PF9: MCU (CN6.45 U4.10), LCD_MicroSD_Flash (R303.2)
PF10: MCU (CN6.47 U4.11), MotorCtrl (CN4.23)
RESET#: MCU (6 pins), JTAG&Trace (RS1.3), ST_LINK (U15.18), Audio (R304.2), LCD_MicroSD_Flash (TR3.1)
